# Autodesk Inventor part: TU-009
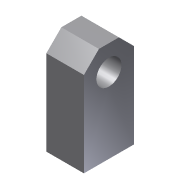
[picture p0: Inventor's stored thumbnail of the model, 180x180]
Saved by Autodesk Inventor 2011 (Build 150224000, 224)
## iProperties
Created: 2009-11
Part Number: TU-009
Document SubType Name: Modeling
Designer: t_jahrl
Density: 1 g/cm^3
Description: Rod Eye
Mass: 9.50433 g
Surface Area: 39.7759 cm^2
Volume: 9.50433 cm^3
Author: t_jahrl
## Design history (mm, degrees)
sketch "Sketch1"
  geometry: L1 (-10, 10)-(-10, -30); L2 (-10, -30)-(10, -30); L3 (10, -30)-(10, 10); L4 (10, 10)-(-10, 10); C1 r 5 at (0, 0); 1 further point
  constraints: 8 end point, 2 perpendicular, 1 centre point, 1 coincident, 1 parallel, 1 vertical
  dimensions: "Pin_Dia" = 10 diameter of C1; "d1" = 20 distance of L1.end L2.end (= 2 x Pin_Dia); "d2" = 10 horizontal distance of L2.end point (0, 0) (= 0.5 x d1); "d3" = 30 distance from line of L2 point (0, 0) (= 3 x Pin_Dia); "d4" = 10 distance from line of point (0, 0) L4 (= Pin_Dia)
extrude "Extrusion1" new body sketch "Sketch1" stored distance "d5" = 15 (= 1.5 x Pin_Dia); taper "d6" = 0 deg
chamfer "Chamfer1" distance "d7" = 6 (= 0.6 x Pin_Dia); stored, may be unused: second distance "d8" = 2, angle "d9" = 45 deg
sketch "Sketch2"
  geometry: 1 further point
hole "Hole1" sketch "Sketch2" at (10, -7.5) diameter "d10" = 6.917; stored, may be unused: countersink angle "d14" = 90 deg, drill point angle "d16" = 118 deg; dims "d11" = 15 (= 1.5 x Pin_Dia), "d12" = 4, "d13" = 2, "d15" = 20 (= 2 x Pin_Dia)
body "Solid1"
